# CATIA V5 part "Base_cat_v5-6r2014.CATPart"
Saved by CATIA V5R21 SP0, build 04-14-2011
Part number: Base
Bounding box of the stored display mesh (mm): x -32 to 32, y 0 to 144, z 0 to 52
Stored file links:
  D:\CATIA V5R21 E-RESOURCES\CATIA-V5R21\catia-v5r21-Tut\c16-catia-v5r21-tut\c16-catia-v5r21-tut01\Base_cat_v5r21.CATPart
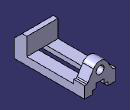
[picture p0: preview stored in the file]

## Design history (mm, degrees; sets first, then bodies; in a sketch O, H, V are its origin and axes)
Body1 (main body)
  Sketch1 on xy-plane, origin (0, 0, 0), H (1, 0, 0), V (0, 1, 0)
    point P1 (-32, 0)
    line L1 (-32, 0) -> (32, 0)
    line L2 (32, 0) -> (32, 144)
    line L3 (32, 144) -> (-32, 144)
    line L4 (-32, 144) -> (-32, 0)
    length L1 = 64
    length L2 = 144
    distance V L2 = 32
    coincidence: P1 H
    horizontal: L1 H, L3 H
    vertical: L2 V, L4 V
  Pad1: profile Sketch1, direction (0, 0, 1), length 16
  Sketch2 on face of Pad1, origin (32, 0, 0), H (0, 1, 0), V (0, 0, 1)
    point P1 (0, 16)
    line L1 (0, 16) -> (0, 36)
    point P2 (0, 36)
    line L2 (26, 52) -> (26, 16)
    line L3 (26, 16) -> (0, 16)
    reference projected line E1 (144, 16) -> (0, 16) from edge of Pad1
    line L4 (26, 52) -> (16, 52)
    point P5 (16, 52)
    line L5 (16, 52) -> (0, 36)
    length L2 = 36
    distance P5 P2 H = 16
    distance P5 P2 V = 16
    length L3 = 26
    coincidence: P1 V, E1 L3
    vertical: L1 V, L2 V
    horizontal: L3 H, L4 H
  Pad2: profile Sketch2, direction (-1, 0, 0), length 64
  Sketch3 on face of Pad1, origin (0, 144, 0), H (-1, 0, 0), V (0, 0, 1)
    line L1 (-32, 16) -> (-32, 24)
    point P2 (32, 24)
    line L2 (32, 24) -> (32, 16)
    line L3 (32, 16) -> (-32, 16)
    reference projected line E1 (32, 16) -> (-32, 16) from edge of Pad1
    line L4 (32, 24) -> (26, 24)
    point P4 (26, 24)
    line L5 (26, 24) -> (13.6777, 44.3018)
    point P5 (0, 52)
    line L6 (-13.6777, 44.3018) -> (-26, 24)
    point P6 (-26, 24)
    line L7 (-26, 24) -> (-32, 24)
    reference projected line E2 (32, 52) -> (-32, 52) from edge of Pad2
    reference projected line E3 (32, 16) -> (32, 52) from edge of Pad2
    reference projected line E4 (-32, 0) -> (-32, 16) from edge of Pad1
    arc A1 centre (0, 36) radius 16 from (13.6777, 44.3018) to (-13.6777, 44.3018) ccw
    point P8 (0, 36)
    reference projected line E5 (32, 52) -> (-32, 52) from edge of Pad2
    circle A2 centre (0, 36) radius 8
    distance H P2 = 24
    distance P6 P4 = 52
    distance P6 V = 26
    radius A1 = 16
    radius A2 = 8
    vertical: L1 V, L2 V
    horizontal: L3 H, L4 H, L7 H
    coincidence: L3 E1, P5 V, P6 L4, P5 E2, L2 E3, L1 E4, P8 V
    tangency: A1 E5, L6 A1, A1 L5
  Pad3: profile Sketch3, direction (0, -1, 0), length 22
  Fillet1: radius 3, on 2 edges
  Sketch4 on face of Pad1, origin (0, 144, 0), H (-1, 0, 0), V (0, 0, 1)
    point P1 (-16, 0)
    line L1 (-16, 0) -> (-16, 7)
    point P2 (-16, 7)
    line L2 (-16, 7) -> (-8, 7)
    point P3 (-8, 7)
    line L3 (-8, 7) -> (-8, 16)
    point P4 (-8, 16)
    line L4 (-8, 16) -> (0, 16)
    point P5 (0, 16)
    point P6 (16, 7)
    point P7 (16, 0)
    line L5 (16, 0) -> (16, 7)
    point P8 (8, 7)
    line L6 (16, 7) -> (8, 7)
    point P9 (8, 16)
    line L7 (8, 7) -> (8, 16)
    point P10 (0, 16)
    line L8 (8, 16) -> (0, 16)
    line L9 (-16, 0) -> (16, 0)
    point P11 (16, 0)
    distance L1 V = 16
    distance L3 V = 8
    distance H L4 = 16
    distance H L2 = 7
    coincidence: P1 H, P5 V, P7 P11, P5 P10
    vertical: L1 V, L3 V
    horizontal: L2 H, L4 H, L9 H
    symmetry: P2 P6 V, P1 P7 V, L1 L5 V, P3 P8 V, L2 L6 V, P4 P9 V, L3 L7 V, P5 P10 V, L4 L8 V
  Pocket1: profile Sketch4, direction (0, -1, 0), through (limit type 3)
  Sketch5 on face of Pad1, origin (0, 0, 0), H (1, 0, 0), V (0, -1, 0)
    circle A1 centre (22, -38) radius 3
    point P1 (22, -38)
    reference projected line E1 (32, 0) -> (-32, 0) from edge of Pad1
    radius A1 = 3
    distance P1 E1 = 38
    distance V P1 = 22
  Pocket2: profile Sketch5, direction (0, 0, 1), length 12
  RectPattern1: of Pocket2, direction 1 instances 2, spacing 70, along edge of Pad1, direction 2 instances 2, spacing 44, along edge of Pad1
